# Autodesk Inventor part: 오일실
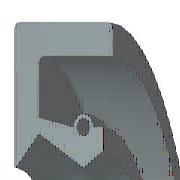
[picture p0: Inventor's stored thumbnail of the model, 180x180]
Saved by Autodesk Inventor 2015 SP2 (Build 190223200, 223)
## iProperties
IsCustomPart: 0
Created: 2009-02
Part Number: 오일실
Material: 고무
Description: 오일-실
Document SubType Name: Modeling
Standard: KS B 2804
Designer: KYOUNG IL JANG
Standards Organization: KS
Language: ko-KR
Size Designation: D - 20 32 8
Categories: <MemberInstance><Categories><Category DisplayName="샤프트 부품" InternalName="7f7aeb1f-a693-4053-b835-cee3144e0d98" Mnemonic="SHFT"><Category DisplayName="실링" Intern
Density: 0.93 g/cm^3
Mass: 2.19344 g
Surface Area: 31.4782 cm^2
Volume: 2.35853 cm^3
Appearance: 고무 - 검은색 - 버전 1.1
Author: KYOUNG IL JANG
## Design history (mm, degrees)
revolve "본체" stored, may be unused: angle "d17" = 90 deg
revolve "스프링1" stored, may be unused: angle "d18" = 90 deg
body "Solid1"
sketch "스케치1"
  geometry: L1 (0, 16)-(8, 16); L2 (8, 14.25)-(1.75, 14.25); L3 (1.75, 11.75)-(4.9, 10); L4 (4.9, 10)-(0, 10); L5 (0, 0)-(9.586, 0) reference; L6 (4.9, 10)-(6.3, 10.875); L7 (0, 18)-(0, -3) reference; L8 (-1.941, 0)-(11.507, 0) reference; L9 (4.2, 12.1)-(1.75, 12.71); L10 (1.75, 12.71)-(1.75, 14.25); L11 (0, 16)-(0, 10.088); L12 (4.9, 10)-(0, 10); L13 (1.75, 11.75)-(0.152, 10.028); L14 (8, 16)-(8, 14.25); L15 (5.6, 12.1)-(6.3, 12.1); L16 (6.3, 12.1)-(6.3, 10.875); C1 r 0.455 at (4.9, 12.1); A1 r 0.7 centre (4.9, 12.1) between (5.6, 12.1) and (4.2, 12.1); A2 r 0.088 centre (0.088, 10.088) between (0, 10.088) and (0.152, 10.028); 1 further point
  constraints: 28 end point, 5 horizontal alignment, 5 point on line, 4 point on circle, 4 vertical alignment, 3 centre point, 3 tangent, 2 collinear, 2 horizontal, 2 perpendicular, 1 coincident, 1 parallel
  dimensions: "d0" = 32 diameter of L1 L5 (= SD2); "d1" = 1.75 distance of L1.end L2.start (= SD); "d2" = 0.91 diameter of C1 (= SPDI); "d3" = 1.4 diameter of A1 (= SPDA); "d4" = 20 diameter of L3.end L5 (= NND); "d5" = 23.5 diameter of L3.start L5 (= TKDM); "d7" = 25.42 diameter of L9.end L5 (= TKDM + 0.24 x SWDT); "d8" = 1.75 distance between parallel lines of L11 L10 (= SD); "d9" = 4.9 distance from line of L11 C1.centre (= SPDST); "d10" = 24.2 diameter of C1.centre L5 (= HLDM); "d11" = 0.0875 radius of A2 (= 0.25 x LAB); "d12" = 6.3 distance between parallel lines of L11 L16 (= SDI); "d13" = 21.75 diameter of L6.end L5 (= ABDM); "d14" = 8 distance from line of L11 L1.end (= SWDT)
fillet "모깎기1" dims "d6" = 0.3 (= RR)
other parameters: "SD2" = 32 [user parameter; used in 1 equation term], "SWDT" = 8 [user parameter; used in 2 equation terms], "RR" = 0.3 [user parameter; used in 1 equation term], "SD" = 1.75 [user parameter; used in 2 equation terms], "NND" = 20 [user parameter; used in 1 equation term], "SPDA" = 1.4 [user parameter; used in 1 equation term], "SPDI" = 0.91 [user parameter; used in 1 equation term], "TKDM" = 23.5 [user parameter; used in 2 equation terms], "HLDM" = 24.2 [user parameter; used in 1 equation term], "ABDM" = 21.75 [user parameter; used in 1 equation term], "SDI" = 6.3 [user parameter; used in 1 equation term], "SPDST" = 4.9 [user parameter; used in 1 equation term], "LAB" = 0.35 [user parameter; used in 1 equation term], "d15" = 0, "d16" = 0, "d19" = 0
